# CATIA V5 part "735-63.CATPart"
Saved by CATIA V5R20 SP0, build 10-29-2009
Part number: 735-63
Bounding box of the stored display mesh (mm): x -47.5 to 47.5, y -47.5 to 47.5, z -60 to 56
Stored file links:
  C:\Users\Utente\Desktop\IO LAVORO\3D X SITO CF\X SITO\735\735-63.CATPart
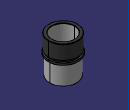
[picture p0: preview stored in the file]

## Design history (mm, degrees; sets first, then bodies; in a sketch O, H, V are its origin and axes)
Set1
  DatumSurface1 to DatumSurface25 "735-63"
Body1 (main body)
